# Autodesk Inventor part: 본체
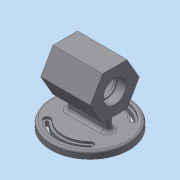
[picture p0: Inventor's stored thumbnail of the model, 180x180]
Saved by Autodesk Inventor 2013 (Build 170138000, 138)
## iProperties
Created: 2017-06
Part Number: 본체
Material: 일반
Document SubType Name: Modeling
Designer: Administrator
Density: 1 g/cm^3
Author: Administrator
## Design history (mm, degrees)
sketch "스케치1" dims "d0" = 60
  geometry: L1 (17.321, 30)-(34.641, 0); L2 (34.641, 0)-(17.321, -30); L3 (17.321, -30)-(-17.321, -30); L4 (-17.321, -30)-(-34.641, 0); L5 (-34.641, 0)-(-17.321, 30); L6 (-17.321, 30)-(17.321, 30); 4 further points
  constraints: 12 end point, 2 coincident, 2 vertical alignment, 1 midpoint, 15 other
extrude "돌출1" new body sketch "스케치1" stored distance "d1" = 70; taper "d2" = 0 deg
sketch "스케치2"
  geometry: 1 further point
hole "구멍1" sketch "스케치2" at (0, 0) diameter "d3" = 28; stored, may be unused: countersink angle "d7" = 90 deg, drill point angle "d9" = 118 deg; dims "d4" = 6, "d5" = 4, "d6" = 2, "d8" = 8
hole "구멍2" diameter "d12" = 32; stored, may be unused: countersink angle "d16" = 90 deg, drill point angle "d18" = 0 deg; dims "d10" = 10, "d11" = 10, "d13" = 6, "d14" = 4, "d15" = 2, "d17" = 12
sketch "스케치3"
  geometry: L1 (17.321, 30)-(34.641, 0) reference; L2 (34.641, 0)-(17.321, -30) reference; L3 (17.321, -30)-(-17.321, -30) reference; L4 (-17.321, -30)-(-34.641, 0) reference; L5 (-34.641, 0)-(-17.321, 30) reference; L6 (-17.321, 30)-(17.321, 30) reference; C1 r 25 at (0, 0); C2 r 14 at (0, 0) reference; 1 further point
  constraints: 1 centre point, 1 coincident
  dimensions: "d19" = 50 diameter of C1
extrude "돌출2" cut sketch "스케치3" stored distance "d20" = 40; taper "d21" = 0 deg
node "작업 평면1"
sketch "스케치4"
  geometry: C1 r 55 at (0, 0); 1 further point
  constraints: 1 centre point, 1 coincident
  dimensions: "d23" = 110 diameter of C1
extrude "돌출3" join sketch "스케치4" distance "d24" = 10; taper "d25" = 0 deg
sketch "스케치5"
  geometry: L1 (0, 0)-(33.941, 33.941); L2 (0, 0)-(48, 0); L3 (0, 0)-(-33.941, 33.941); L4 (0, 0)-(48, 0); C1 r 55 at (0, 0) reference; A1 r 43 centre (0, 0) between (30.406, 30.406) and (-30.406, 30.406); A2 r 38 centre (0, 0) between (-26.87, 26.87) and (26.87, 26.87); A3 r 48 centre (0, 0) between (-33.941, 33.941) and (33.941, 33.941); A4 r 5 centre (30.406, 30.406) between (33.73, 26.67) and (33.941, 33.941); A5 r 5 centre (-30.406, 30.406) between (-33.941, 33.941) and (-26.87, 26.87); A6 r 38 centre (0, 0) between (26.87, 26.87) and (-26.87, 26.87); A7 r 48 centre (0, 0) between (33.941, 33.941) and (-33.941, 33.941); A8 r 5 centre (-30.406, 30.406) between (-26.67, 33.73) and (-33.941, 33.941); A9 r 5 centre (-30.406, 30.406) between (-26.87, 26.87) and (-26.67, 33.73); A10 r 5 centre (30.406, 30.406) between (26.87, 26.87) and (33.73, 26.67); A11 r 5 centre (30.406, 30.406) between (33.941, 33.941) and (26.87, 26.87)
  constraints: 26 point on circle, 11 centre point, 8 end point, 3 coincident, 3 point on line, 2 equal length, 2 horizontal, 1 perpendicular
  dimensions: "d26" = 86 diameter of A1; "d27" = 76 diameter of A2; "d28" = 96 diameter of A3; "d30" = 45 deg angle of L2 L1; "d31" = 48 distance of L1.start L3.end; "d32" = 135 deg angle of L4 L3 (derived); "d33" = 10 diameter of A5
extrude "돌출4" cut sketch "스케치5" distance "d34" = 3; taper "d35" = 0 deg
sketch "스케치6"
  geometry: A1 r 38 centre (0, 0) between (26.87, 26.87) and (-26.87, 26.87) reference; A2 r 5 centre (-30.406, 30.406) between (-33.941, 33.941) and (-26.87, 26.87) reference; A3 r 48 centre (0, 0) between (33.941, 33.941) and (-33.941, 33.941) reference; A4 r 5 centre (30.406, 30.406) between (26.87, 26.87) and (33.941, 33.941) reference; A5 r 45 centre (0, 0) between (31.82, 31.82) and (-31.82, 31.82); A6 r 2 centre (-30.406, 30.406) between (-31.82, 31.82) and (-28.991, 28.991); A7 r 41 centre (0, 0) between (28.991, 28.991) and (-28.991, 28.991); A8 r 2 centre (30.406, 30.406) between (28.991, 28.991) and (31.82, 31.82)
  constraints: 8 point on circle, 4 centre point, 3 other
  dimensions: "d38" = 4 radial gap between concentric circles of A7 A5
extrude "돌출5" cut sketch "스케치6" stored distance "d40" = 3; taper "d41" = 0 deg
sketch "스케치7"
  geometry: L1 (-24, 5)-(24, 5); L2 (24, 5)-(24, -5); L3 (24, -5)-(-24, -5); L4 (-24, -5)-(-24, 5); L5 (-24, 5)-(24, -5); L6 (24, 5)-(-24, -5); C1 r 55 at (0, 0) reference; 2 further points
  constraints: 12 end point, 4 midpoint, 2 parallel, 2 vertical alignment, 1 horizontal, 1 perpendicular, 4 other
  dimensions: "d42" = 48 distance of L1.start L1.end; "d44" = 10 distance of L1.end L2.end
extrude "돌출6" join sketch "스케치7" stored distance "d45" = 3; taper "d46" = 0 deg
fillet "모깎기1" dims "d47" = 5
fillet "모깎기2" dims "d48" = 3
node "솔리드1"
mirror "대칭1"
mirror "대칭2"
node "절단 모서리 투영1"
other parameters: "d22" = -62
